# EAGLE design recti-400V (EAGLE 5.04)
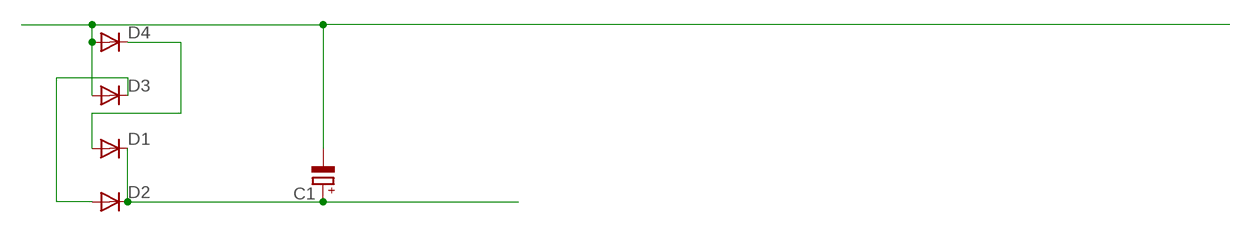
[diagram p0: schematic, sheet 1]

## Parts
C1  CPOL-EUE5-8.5  [E5-8,5]
D1  DIODE-D-5  [D-5]
D2  DIODE-D-5  [D-5]
D3  DIODE-D-5  [D-5]
D4  DIODE-D-5  [D-5]

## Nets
N$1: C1.- D3.A D4.A
N$20: C1.+ D1.C D2.C
N$25: D1.A D4.C
N$26: D2.A D3.C

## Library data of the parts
C1 = rcl-2:CPOL-EU: POLARIZED CAPACITOR, European symbol
D1-D4 = diode-1:DIODE-: DIODE

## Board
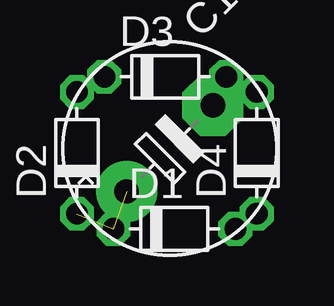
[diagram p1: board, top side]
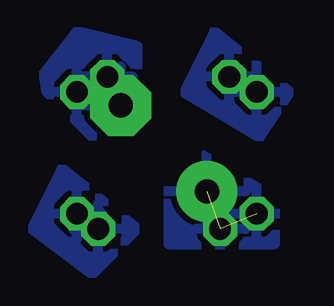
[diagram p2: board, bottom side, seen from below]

No outline drawn. Coordinates in mm, seen from the top.
Copper layers (1*16): Top 0.035mm / dielectric 1.5mm / Bottom 0.035mm
Design rules "default": minimum track width 10mil, minimum drill 24mil, track to track 8mil, track to pad 8mil, pad to pad 8mil, via to via 8mil, smd to smd 8mil, copper to edge 40mil, drill to drill 8mil, minimum pad ring 10mil, minimum via ring 8mil, stop-mask expansion 4mil, vias tented up to drill 0mil, thermal gap 10mil

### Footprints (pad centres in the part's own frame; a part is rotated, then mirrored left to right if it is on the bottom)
E5-8,5 = drill 1.016 pad 2.54 round: + -2.54,0 | drill 1.016 pad 2.54 octagon: - 2.54,0
D-5 = drill 0.9 octagon: A 2.54,0; C -2.54,0

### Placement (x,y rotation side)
C1  5.27,4.63 45 top
D1  5.46,1.27 0 top
D2  1.4,4.45 90 top
D3  5.08,7.62 0 top
D4  8.89,4.45 90 top

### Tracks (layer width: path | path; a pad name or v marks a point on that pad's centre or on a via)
N$1
  pour Bottom (isolate 1.016): 10.16,6.99 8.26,5.08 6.35,6.35 6.35,8.89 8.89,9.53 10.29,7.75
N$20  (2 unrouted)
  pour Bottom (isolate 1.016): 0.64,2.54 3.81,4.45 5.08,3.17 5.08,0.64 0.64,0.64
N$25
  pour Bottom (isolate 1.016, rank 2): 6.35,1.27 9.53,3.81 10.79,1.27 8.26,-0.64
N$26
  pour Bottom (isolate 1.016, rank 2): 0,6.99 3.17,9.53 4.45,6.99 1.27,5.08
